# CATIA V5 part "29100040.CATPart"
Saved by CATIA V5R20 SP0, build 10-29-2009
Part number: 29100040
Definition: NONE
Nomenclature: 29100040
Source: Unknown
Description: 29100040
Bounding box of the stored display mesh (mm): x -20 to 44.548, y -64 to 98.548, z -54 to 54
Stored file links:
  C:\Users\Utente\Desktop\IO LAVORO\3D X SITO CF\X SITO\PLASTICA\RF1\29100040.CATPart

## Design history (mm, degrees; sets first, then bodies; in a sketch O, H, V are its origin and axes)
Body1 "29100040" (main body)
  Solid1: solid without history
